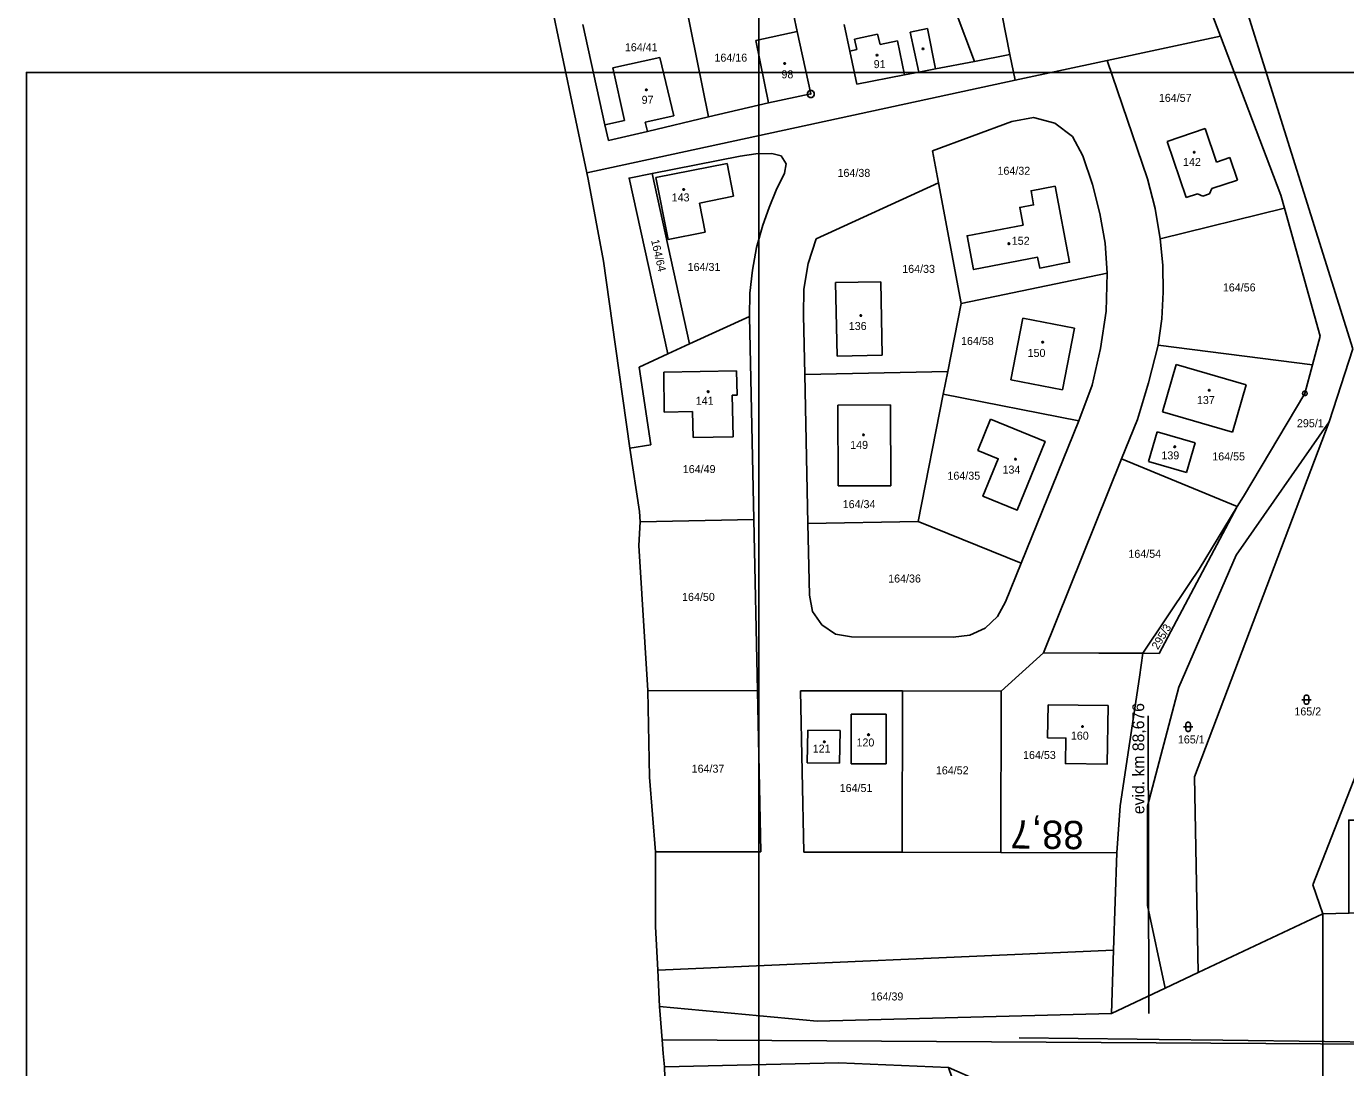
# Model space of a CAD drawing. Extents: x -780000 to -777378, y -1011169 to -1009297.
# Drawn here: x -779530.7 to -779250.3, y -1010479.3 to -1010258.1 of the extents above; entities that cross this region are included whole.
import ezdxf

# ---------------------------------------------------------------- set-up
doc = ezdxf.new("R2010")
doc.units = 0
for name, color, linetype in [('Default', 7, 'Continuous'), ('KLADY_ZMVM', 7, 'Continuous'), ('KN_HRANICE', 7, 'Continuous'), ('KN_KULTURY', 7, 'Continuous'), ('KN_PARCELY', 7, 'Continuous'), ('KN_SLUCKY', 7, 'Continuous'), ('KN_VEDENI', 7, 'Continuous'), ('LEGENDA', 7, 'Continuous'), ('obvod_stavby', 7, 'Continuous'), ('staničení', 7, 'Continuous'), ('Vrstva 7', 7, 'Continuous'), ('Železniční svršek', 7, 'Continuous')]:
    doc.layers.add(name, color=color, linetype=linetype)

# ---------------------------------------------------------------- blocks, each defined once
blk = doc.blocks.new('101')
at = {"layer": 'Default'}
blk.add_line((-0.05, 0), (0.05, 0), dxfattribs=at)
blk.add_lwpolyline([(0.19, 0.72), (0.53, 0.53), (0.72, 0.19), (0.72, -0.2), (0.53, -0.54), (0.19, -0.73), (-0.2, -0.73), (-0.54, -0.54), (-0.73, -0.2), (-0.73, 0.19), (-0.54, 0.53), (-0.2, 0.72), (0.19, 0.72)], dxfattribs=at)
blk = doc.blocks.new('316')
at = {"layer": 'Default'}
for points in [[(-1, 1), (0.27, 1), (1, 1)], [(-0.5, 1.5), (-0.4, 1.79), (-0.15, 1.97), (0.16, 1.97), (0.41, 1.79), (0.51, 1.5), (0.51, 0.5), (0.41, 0.21), (0.16, 0.03), (-0.15, 0.03), (-0.4, 0.21), (-0.5, 0.5), (-0.5, 1.5)]]:
    blk.add_lwpolyline(points, dxfattribs=at)
blk = doc.blocks.new('402')
at = {"layer": 'Default'}
blk.add_lwpolyline([(0.09, 0.15), (0.18, 0), (0.09, -0.15), (-0.09, -0.15), (-0.18, 0), (-0.09, 0.15), (0.09, 0.15)], dxfattribs=at)
blk = doc.blocks.new('105')
at = {"layer": 'Default'}
blk.add_line((-0.12, 0), (0.12, 0), dxfattribs=at)
blk.add_lwpolyline([(0.15, 0.48), (0.4, 0.3), (0.5, 0.01), (0.4, -0.28), (0.15, -0.46), (-0.16, -0.46), (-0.41, -0.28), (-0.51, 0.01), (-0.41, 0.3), (-0.16, 0.48), (0.15, 0.48)], dxfattribs=at)

msp = doc.modelspace()

# ---------------------------------------------------------------- linework, layer by layer
at = {"layer": 'KLADY_ZMVM'}
msp.add_lwpolyline([(-779375, -1010000), (-779375, -1010500), (-779108.78, -1010500)], dxfattribs=at)
at = {"layer": 'KN_HRANICE'}
for p, q in [((-779411.57, -1010289.24), (-779423.17, -1010234.28)), ((-779321.68, -1010264.11), (-779327.59, -1010234.13)), ((-779248.83, -1010326.61), (-779275.45, -1010241.64)), ((-779369.26, -1010248.05), (-779366.85, -1010259.23)), ((-779385.75, -1010277.38), (-779390.67, -1010252.85)), ((-779333.07, -1010255.29), (-779329.22, -1010265.58)), ((-779276.95, -1010260.2), (-779278.89, -1010255.08)), ((-779412.45, -1010257.73), (-779407.72, -1010279.08)), ((-779375.67, -1010261.12), (-779366.85, -1010259.23)), ((-779366.85, -1010259.23), (-779363.99, -1010272.5)), ((-779356.9, -1010257.72), (-779355.68, -1010263.39)), ((-779372.96, -1010274.36), (-779375.67, -1010261.12)), ((-779276.95, -1010260.2), (-779300.99, -1010265.39)), ((-779264.13, -1010293.98), (-779276.95, -1010260.2)), ((-779406.08, -1010266.98), (-779396.07, -1010264.73)), ((-779396.07, -1010264.73), (-779393.09, -1010277.12)), ((-779355.68, -1010263.39), (-779354.17, -1010270.43)), ((-779329.22, -1010265.58), (-779321.68, -1010264.11)), ((-779321.68, -1010264.11), (-779320.52, -1010269.6)), ((-779406.08, -1010266.98), (-779403.57, -1010278.12)), ((-779344.05, -1010268.46), (-779341.01, -1010267.87)), ((-779341.01, -1010267.87), (-779337.47, -1010267.18)), ((-779337.47, -1010267.18), (-779329.22, -1010265.58)), ((-779300.99, -1010265.39), (-779320.52, -1010269.6)), ((-779292.43, -1010290.53), (-779300.99, -1010265.39)), ((-779320.52, -1010269.6), (-779362.78, -1010278.71)), ((-779354.17, -1010270.43), (-779344.05, -1010268.46)), ((-779363.99, -1010272.5), (-779372.96, -1010274.36)), ((-779372.96, -1010274.36), (-779385.75, -1010277.38)), ((-779362.78, -1010278.71), (-779411.57, -1010289.24)), ((-779407.72, -1010279.08), (-779403.57, -1010278.12)), ((-779407.72, -1010279.08), (-779406.99, -1010282.4)), ((-779399.16, -1010278.51), (-779393.09, -1010277.12)), ((-779399.16, -1010278.51), (-779398.69, -1010280.44)), ((-779385.75, -1010277.38), (-779398.69, -1010280.44)), ((-779321.24, -1010278.36), (-779338.14, -1010284.55)), ((-779316.65, -1010277.51), (-779321.24, -1010278.36)), ((-779312.1, -1010278.67), (-779316.65, -1010277.51)), ((-779308.36, -1010281.51), (-779312.1, -1010278.67)), ((-779398.69, -1010280.44), (-779406.99, -1010282.4)), ((-779306.17, -1010285.63), (-779308.36, -1010281.51)), ((-779280.15, -1010279.85), (-779288.27, -1010282.58)), ((-779277.75, -1010286.96), (-779280.15, -1010279.85)), ((-779338.14, -1010284.55), (-779336.86, -1010291.37)), ((-779288.27, -1010282.58), (-779284.23, -1010294.51)), ((-779397.7, -1010289.41), (-779379.01, -1010285.72)), ((-779396.93, -1010290.27), (-779381.75, -1010287.29)), ((-779381.75, -1010287.29), (-779380.38, -1010294.23)), ((-779379.01, -1010285.72), (-779375.64, -1010285.2)), ((-779375.64, -1010285.2), (-779372.24, -1010285.16)), ((-779372.24, -1010285.16), (-779370.29, -1010285.62)), ((-779370.29, -1010285.62), (-779369.18, -1010287.35)), ((-779369.18, -1010287.35), (-779369.57, -1010289.31)), ((-779304.1, -1010291.71), (-779306.17, -1010285.63)), ((-779274.91, -1010286.01), (-779277.75, -1010286.96)), ((-779273.29, -1010290.79), (-779274.91, -1010286.01)), ((-779411.29, -1010290.56), (-779411.57, -1010289.24)), ((-779389.74, -1010325.58), (-779397.7, -1010289.41)), ((-779394.32, -1010303.41), (-779396.93, -1010290.27)), ((-779369.57, -1010289.31), (-779371.31, -1010292.92)), ((-779408.01, -1010308), (-779411.29, -1010290.56)), ((-779371.31, -1010292.92), (-779372.85, -1010296.61)), ((-779336.86, -1010291.37), (-779362.87, -1010303.27)), ((-779336.86, -1010291.37), (-779332.05, -1010316.98)), ((-779302.56, -1010297.89), (-779304.1, -1010291.71)), ((-779292.43, -1010290.53), (-779290.82, -1010296.83)), ((-779279.24, -1010293.68), (-779278.8, -1010292.6)), ((-779278.8, -1010292.6), (-779273.29, -1010290.79)), ((-779380.38, -1010294.23), (-779387.63, -1010295.67)), ((-779387.63, -1010295.67), (-779386.44, -1010301.84)), ((-779284.23, -1010294.51), (-779281.79, -1010293.68)), ((-779281.79, -1010293.68), (-779280.65, -1010294.17)), ((-779280.65, -1010294.17), (-779279.24, -1010293.68)), ((-779263.36, -1010296.74), (-779264.13, -1010293.98)), ((-779372.85, -1010296.61), (-779374.18, -1010300.38)), ((-779301.46, -1010304.17), (-779302.56, -1010297.89)), ((-779290.82, -1010296.83), (-779289.73, -1010303.24)), ((-779263.36, -1010296.74), (-779289.73, -1010303.24)), ((-779255.74, -1010323.95), (-779263.36, -1010296.74)), ((-779374.18, -1010300.38), (-779375.49, -1010305.12)), ((-779386.44, -1010301.84), (-779394.32, -1010303.41)), ((-779362.87, -1010303.27), (-779364.55, -1010308.53)), ((-779301, -1010310.57), (-779301.46, -1010304.17)), ((-779289.73, -1010303.24), (-779289.19, -1010308.89)), ((-779375.49, -1010305.12), (-779376.4, -1010309.95)), ((-779406.22, -1010321.12), (-779408.01, -1010308)), ((-779376.4, -1010309.95), (-779376.91, -1010314.83)), ((-779364.55, -1010308.53), (-779365.44, -1010313.99)), ((-779289.19, -1010308.89), (-779289.09, -1010314.57)), ((-779358.71, -1010312.55), (-779349.07, -1010312.38)), ((-779358.39, -1010328.18), (-779358.71, -1010312.55)), ((-779349.07, -1010312.38), (-779348.8, -1010328.01)), ((-779332.05, -1010316.98), (-779301, -1010310.57)), ((-779301.2, -1010318.61), (-779301, -1010310.57)), ((-779376.91, -1010314.83), (-779376.98, -1010319.73)), ((-779365.44, -1010313.99), (-779365.52, -1010319.51)), ((-779289.09, -1010314.57), (-779289.42, -1010320.24)), ((-779334.89, -1010331.42), (-779332.05, -1010316.98)), ((-779402.4, -1010347.73), (-779406.22, -1010321.12)), ((-779376.98, -1010319.73), (-779389.74, -1010325.58)), ((-779376.98, -1010319.73), (-779376.08, -1010362.91)), ((-779365.52, -1010319.51), (-779365.26, -1010332.05)), ((-779321.5, -1010333.19), (-779318.95, -1010320.1)), ((-779318.95, -1010320.1), (-779307.92, -1010322.25)), ((-779302.4, -1010326.55), (-779301.2, -1010318.61)), ((-779289.42, -1010320.24), (-779290.15, -1010325.87)), ((-779307.92, -1010322.25), (-779310.5, -1010335.33)), ((-779257.37, -1010330.02), (-779255.74, -1010323.95)), ((-779394.39, -1010327.71), (-779389.74, -1010325.58)), ((-779304.22, -1010334.38), (-779302.4, -1010326.55)), ((-779290.15, -1010325.87), (-779292.21, -1010333.83)), ((-779257.37, -1010330.02), (-779290.15, -1010325.87)), ((-779253.82, -1010342.15), (-779248.83, -1010326.61)), ((-779400.48, -1010330.51), (-779394.39, -1010327.71)), ((-779348.8, -1010328.01), (-779358.39, -1010328.18)), ((-779397.95, -1010347.05), (-779400.48, -1010330.51)), ((-779395.24, -1010331.56), (-779379.78, -1010331.29)), ((-779395.11, -1010340.07), (-779395.24, -1010331.56)), ((-779379.78, -1010331.29), (-779379.66, -1010336.48)), ((-779365.26, -1010332.05), (-779334.89, -1010331.42)), ((-779365.26, -1010332.05), (-779364.6, -1010363.75)), ((-779335.84, -1010336.25), (-779334.89, -1010331.42)), ((-779289.25, -1010340.01), (-779286.34, -1010329.98)), ((-779286.34, -1010329.98), (-779271.46, -1010334.31)), ((-779259, -1010336.11), (-779257.37, -1010330.02)), ((-779310.5, -1010335.33), (-779321.5, -1010333.19)), ((-779307.01, -1010341.91), (-779304.22, -1010334.38)), ((-779292.21, -1010333.83), (-779294.54, -1010341.64)), ((-779271.46, -1010334.31), (-779274.38, -1010344.34)), ((-779379.66, -1010336.48), (-779380.68, -1010336.5)), ((-779380.68, -1010336.5), (-779380.48, -1010345.29)), ((-779341.15, -1010363.28), (-779335.84, -1010336.25)), ((-779335.84, -1010336.25), (-779307.01, -1010341.91)), ((-779272.05, -1010357.97), (-779259, -1010336.11)), ((-779389.11, -1010339.96), (-779395.11, -1010340.07)), ((-779388.99, -1010345.45), (-779389.11, -1010339.96)), ((-779358.24, -1010338.57), (-779347.03, -1010338.54)), ((-779358.16, -1010355.75), (-779358.24, -1010338.57)), ((-779347.03, -1010338.54), (-779346.99, -1010355.72)), ((-779274.38, -1010344.34), (-779289.25, -1010340.01)), ((-779307.01, -1010341.91), (-779319.25, -1010372.13)), ((-779294.54, -1010341.64), (-779297.93, -1010350.03)), ((-779253.82, -1010342.15), (-779282.45, -1010417.52)), ((-779253.82, -1010342.15), (-779273.57, -1010370.48)), ((-779380.48, -1010345.29), (-779388.99, -1010345.45)), ((-779292.22, -1010350.54), (-779290.41, -1010344.29)), ((-779290.41, -1010344.29), (-779282.31, -1010346.63)), ((-779402.4, -1010347.73), (-779397.95, -1010347.05)), ((-779400.35, -1010361.15), (-779402.4, -1010347.73)), ((-779282.31, -1010346.63), (-779284.12, -1010352.88)), ((-779297.93, -1010350.03), (-779314.54, -1010391.18)), ((-779273.36, -1010360.11), (-779297.93, -1010350.03)), ((-779284.12, -1010352.88), (-779292.22, -1010350.54)), ((-779346.99, -1010355.72), (-779358.16, -1010355.75)), ((-779281.48, -1010373.4), (-779273.36, -1010360.11)), ((-779273.36, -1010360.11), (-779272.05, -1010357.97)), ((-779400.24, -1010363.41), (-779400.35, -1010361.15)), ((-779376.08, -1010362.91), (-779400.24, -1010363.41)), ((-779376.08, -1010362.91), (-779375.32, -1010399.25)), ((-779364.6, -1010363.75), (-779341.15, -1010363.28)), ((-779319.25, -1010372.13), (-779341.15, -1010363.28)), ((-779400.52, -1010368.39), (-779400.24, -1010363.41)), ((-779364.6, -1010363.75), (-779364.28, -1010378.98)), ((-779398.58, -1010399.19), (-779400.52, -1010368.39)), ((-779273.57, -1010370.48), (-779285.76, -1010398.5)), ((-779322.59, -1010380.37), (-779319.25, -1010372.13)), ((-779283.54, -1010376.5), (-779281.48, -1010373.4)), ((-779293.41, -1010391.29), (-779283.54, -1010376.5)), ((-779364.28, -1010378.98), (-779363.63, -1010382.4)), ((-779363.63, -1010382.4), (-779361.65, -1010385.29)), ((-779324.28, -1010383.52), (-779322.59, -1010380.37)), ((-779361.65, -1010385.29), (-779358.73, -1010387.21)), ((-779326.93, -1010385.93), (-779324.28, -1010383.52)), ((-779358.73, -1010387.21), (-779355.3, -1010387.79)), ((-779355.3, -1010387.79), (-779333.72, -1010387.84)), ((-779333.72, -1010387.84), (-779330.18, -1010387.47)), ((-779330.18, -1010387.47), (-779326.93, -1010385.93)), ((-779314.54, -1010391.18), (-779323.52, -1010399.33)), ((-779302.76, -1010391.24), (-779314.54, -1010391.18)), ((-779294.13, -1010391.29), (-779302.76, -1010391.24)), ((-779294.17, -1010396.39), (-779293.41, -1010391.29)), ((-779293.41, -1010391.29), (-779294.13, -1010391.29)), ((-779257.31, -1010440.46), (-779238.48, -1010392.35)), ((-779298.26, -1010423.68), (-779294.17, -1010396.39)), ((-779375.32, -1010399.25), (-779398.58, -1010399.19)), ((-779398.25, -1010417.61), (-779398.58, -1010399.19)), ((-779374.61, -1010433.5), (-779375.32, -1010399.25)), ((-779366.19, -1010399.24), (-779365.48, -1010433.52)), ((-779344.47, -1010399.29), (-779366.19, -1010399.24)), ((-779344.55, -1010433.56), (-779344.47, -1010399.29)), ((-779323.52, -1010399.33), (-779344.47, -1010399.29)), ((-779323.6, -1010433.61), (-779323.52, -1010399.33)), ((-779285.76, -1010398.5), (-779292.43, -1010423.76)), ((-779355.43, -1010414.78), (-779355.41, -1010404.25)), ((-779355.41, -1010404.25), (-779347.94, -1010404.25)), ((-779347.94, -1010404.25), (-779347.97, -1010414.8)), ((-779364.63, -1010407.66), (-779364.73, -1010414.54)), ((-779364.63, -1010407.66), (-779357.75, -1010407.71)), ((-779357.86, -1010414.64), (-779357.75, -1010407.71)), ((-779364.73, -1010414.54), (-779357.86, -1010414.64)), ((-779347.97, -1010414.8), (-779355.43, -1010414.78)), ((-779396.98, -1010433.44), (-779398.25, -1010417.61)), ((-779281.67, -1010459.12), (-779282.45, -1010417.52)), ((-779298.95, -1010433.67), (-779298.26, -1010423.68)), ((-779292.43, -1010423.76), (-779292.43, -1010444.9)), ((-779396.98, -1010433.44), (-779374.61, -1010433.5)), ((-779396.97, -1010449.31), (-779396.98, -1010433.44)), ((-779365.48, -1010433.52), (-779344.55, -1010433.56)), ((-779344.55, -1010433.56), (-779323.6, -1010433.61)), ((-779323.6, -1010433.61), (-779298.95, -1010433.67)), ((-779298.95, -1010433.67), (-779299.64, -1010454.37)), ((-779255.18, -1010446.63), (-779257.31, -1010440.46)), ((-779292.43, -1010444.9), (-779288.66, -1010462.42)), ((-779281.67, -1010459.12), (-779255.18, -1010446.63)), ((-779255.18, -1010446.63), (-779223.61, -1010445.86)), ((-779396.51, -1010458.6), (-779396.97, -1010449.31)), ((-779396.51, -1010458.6), (-779299.64, -1010454.37)), ((-779299.64, -1010454.37), (-779300.09, -1010467.81)), ((-779396.12, -1010466.31), (-779396.51, -1010458.6)), ((-779288.66, -1010462.42), (-779281.67, -1010459.12)), ((-779300.09, -1010467.81), (-779288.66, -1010462.42)), ((-779396.12, -1010466.31), (-779362.62, -1010469.45)), ((-779395.56, -1010473.38), (-779396.12, -1010466.31)), ((-779300.09, -1010467.81), (-779362.62, -1010469.45)), ((-779395.32, -1010476.34), (-779395.56, -1010473.38)), ((-779395.1, -1010479.15), (-779395.32, -1010476.34)), ((-779357.99, -1010478.29), (-779395.1, -1010479.15)), ((-779394.26, -1010499.5), (-779395.1, -1010479.15)), ((-779357.99, -1010478.29), (-779334.72, -1010479.27)), ((-779334.72, -1010479.27), (-779323.42, -1010512.4)), ((-779334.72, -1010479.27), (-779328.3, -1010482.13))]:
    msp.add_line(p, q, dxfattribs=at)
for points in [[(-779394.39, -1010327.71), (-779402.61, -1010290.38), (-779397.7, -1010289.41)], [(-779293.41, -1010391.29), (-779289.96, -1010391.32), (-779273.36, -1010360.11)]]:
    msp.add_lwpolyline(points, dxfattribs=at)
for points in [[(-779312.04, -1010292.07), (-779317.19, -1010293.07), (-779316.63, -1010296.07), (-779319.57, -1010296.61), (-779318.86, -1010300.34), (-779330.76, -1010302.6), (-779329.38, -1010309.79), (-779315.8, -1010307.17), (-779315.34, -1010309.48), (-779308.98, -1010308.25)], [(-779325.78, -1010341.59), (-779314.2, -1010346.31), (-779320.16, -1010360.9), (-779327.4, -1010357.94), (-779324.14, -1010349.97), (-779328.48, -1010348.2)], [(-779313.52, -1010402.22), (-779300.8, -1010402.42), (-779301.03, -1010414.86), (-779309.87, -1010414.71), (-779309.77, -1010409.3), (-779313.67, -1010409.23)]]:
    msp.add_lwpolyline(points, close=True, dxfattribs=at)
at = {"layer": 'KN_SLUCKY'}
for p, q in [((-779342.88, -1010259.37), (-779339.21, -1010258.56)), ((-779342.88, -1010259.37), (-779341.01, -1010267.87)), ((-779339.21, -1010258.56), (-779337.47, -1010267.18)), ((-779354.69, -1010260.87), (-779349.8, -1010259.81)), ((-779354.22, -1010263.07), (-779354.69, -1010260.87)), ((-779349.8, -1010259.81), (-779349.27, -1010261.99)), ((-779349.27, -1010261.99), (-779345.55, -1010261.19)), ((-779345.55, -1010261.19), (-779344.05, -1010268.46)), ((-779355.68, -1010263.39), (-779354.22, -1010263.07))]:
    msp.add_line(p, q, dxfattribs=at)
at = {"layer": 'KN_VEDENI'}
msp.add_line((-779395.56, -1010473.38), (-779130.44, -1010475.03), dxfattribs=at)
at = {"layer": 'LEGENDA'}
msp.add_lwpolyline([(-779530.66, -1010687.91), (-778936.66, -1010687.91), (-778936.66, -1010267.91), (-779530.66, -1010267.91)], close=True, dxfattribs=at)
at = {"layer": 'obvod_stavby'}
msp.add_lwpolyline([(-779249.69, -1010446.5), (-779249.69, -1010426.74), (-779238.66, -1010426.74), (-779242.1, -1010401.61), (-779239.48, -1010394.92), (-779235.13, -1010426.74), (-779233.15, -1010426.74), (-779223.61, -1010445.86), (-779200.73, -1010455.74), (-779202.13, -1010460.62), (-779207.48, -1010497.19), (-779226.1, -1010504.31), (-779235.46, -1010501.42), (-779255.21, -1010502.98), (-779255.18, -1010446.63), (-779249.69, -1010446.5)], dxfattribs=at)
at = {"layer": 'staničení'}
msp.add_line((-779292.29, -1010404.57), (-779292.16, -1010467.82), dxfattribs=at)
at = {"layer": 'Železniční svršek'}
for p, q in [((-779294.64, -1010473.27), (-779319.74, -1010472.96)), ((-779289.98, -1010473.32), (-779294.64, -1010473.27)), ((-779276.41, -1010473.48), (-779289.98, -1010473.32)), ((-779254.8, -1010473.76), (-779276.41, -1010473.48)), ((-779233.21, -1010474.03), (-779254.8, -1010473.76))]:
    msp.add_line(p, q, dxfattribs=at)

# ---------------------------------------------------------------- block references
at = {"layer": 'KN_KULTURY'}
for name, p in [('402', (-779349.9, -1010264.27)), ('402', (-779340.15, -1010262.9)), ('402', (-779369.54, -1010266.01)), ('402', (-779398.92, -1010271.64)), ('402', (-779282.53, -1010284.87)), ('402', (-779390.98, -1010292.78)), ('402', (-779321.89, -1010304.29)), ('402', (-779353.36, -1010319.55)), ('402', (-779314.71, -1010325.22)), ('402', (-779385.8, -1010335.73)), ('402', (-779352.77, -1010344.9)), ('402', (-779320.49, -1010350.07)), ('316', (-779258.67, -1010402.15)), ('402', (-779306.25, -1010406.86)), ('316', (-779283.79, -1010407.92)), ('402', (-779361.09, -1010410.08)), ('402', (-779351.72, -1010408.58))]:
    msp.add_blockref(name, p, dxfattribs=at)
at = {"layer": 'KN_KULTURY', "rotation": 100.78327600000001}
for p in [(-779279.33, -1010335.43), (-779286.65, -1010347.44)]:
    msp.add_blockref('402', p, dxfattribs=at)
at = {"layer": 'KN_PARCELY'}
for name, p in [('101', (-779363.97, -1010272.51)), ('105', (-779259, -1010336.11))]:
    msp.add_blockref(name, p, dxfattribs=at)

# ---------------------------------------------------------------- texts
for s, p in [('164/41', (-779403.48, -1010263.42)), ('164/16', (-779384.45, -1010265.63)), ('98', (-779370.22, -1010269.17)), ('91', (-779350.61, -1010267.01)), ('97', (-779399.93, -1010274.59)), ('164/57', (-779290.02, -1010274.17)), ('142', (-779284.89, -1010287.79)), ('164/38', (-779358.3, -1010290.11)), ('164/32', (-779324.31, -1010289.66)), ('143', (-779393.55, -1010295.32)), ('152', (-779321.28, -1010304.53)), ('164/31', (-779390.15, -1010310.09)), ('164/33', (-779344.55, -1010310.5)), ('164/56', (-779276.42, -1010314.44)), ('136', (-779355.91, -1010322.63)), ('164/58', (-779332.06, -1010325.81)), ('150', (-779317.91, -1010328.35)), ('141', (-779388.42, -1010338.5)), ('137', (-779281.93, -1010338.36)), ('295/1', (-779260.68, -1010343.28)), ('149', (-779355.61, -1010347.89)), ('139', (-779289.48, -1010350.11)), ('164/55', (-779278.67, -1010350.33)), ('164/49', (-779391.18, -1010353.02)), ('134', (-779323.24, -1010353.13)), ('164/35', (-779334.94, -1010354.43)), ('164/34', (-779357.2, -1010360.47)), ('164/54', (-779296.5, -1010371.02)), ('164/36', (-779347.54, -1010376.27)), ('164/50', (-779391.34, -1010380.17)), ('165/2', (-779261.22, -1010404.5)), ('160', (-779308.72, -1010409.65)), ('121', (-779363.58, -1010412.4)), ('120', (-779354.27, -1010411.09)), ('165/1', (-779285.98, -1010410.45)), ('164/53', (-779318.88, -1010413.75)), ('164/37', (-779389.3, -1010416.66)), ('164/52', (-779337.4, -1010417.01)), ('164/51', (-779357.84, -1010420.76)), ('164/39', (-779351.27, -1010465.04))]:
    msp.add_text(s, height=1.7, dxfattribs=at).set_placement(p)
for s, rotation, p in [('164/64', 283.041, (-779397.93, -1010303.59)), ('295/3', 59.301, (-779290.22, -1010390.64))]:
    msp.add_text(s, height=1.7, rotation=rotation, dxfattribs=at).set_placement(p)
at = {"layer": 'staničení'}
msp.add_text('evid. km 88,676', height=2.5, rotation=90.1102, dxfattribs=at).set_placement((-779293.1, -1010425.47))
at = {"layer": 'Vrstva 7'}
msp.add_text('88,7', height=6, rotation=179.3038, dxfattribs=at).set_placement((-779305.9, -1010426.93))

doc.saveas('drawing.dxf')
